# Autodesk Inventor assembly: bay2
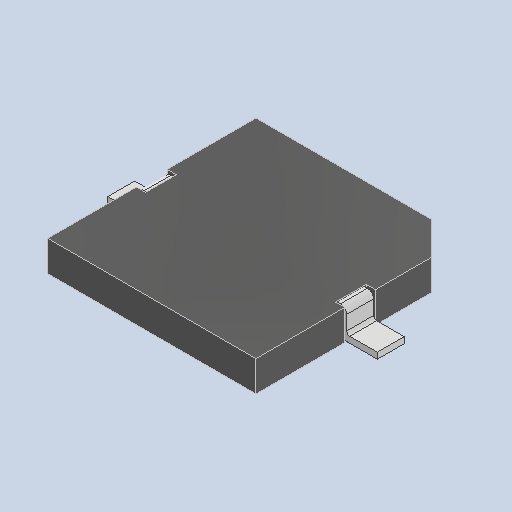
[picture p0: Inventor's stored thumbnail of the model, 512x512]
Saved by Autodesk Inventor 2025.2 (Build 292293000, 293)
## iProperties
Created: 2025-04
Part Number: bay2
Description: PART--DESC
Document SubType Name: Assembly
Designer: BennF
Author: BennF
Revision Number: NONE
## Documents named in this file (3)
- C:\Users\BennF\Nextcloud\Benutzer\CNC JarBeRi\existing parts\Electronics\RepRap A4988 Shied (USE WITHOUT ARDUINO)\reprap-a4988-1.snapshot.1\RepRap\RepRap\bay2_2.iam
- C:\Users\BennF\Nextcloud\Benutzer\CNC JarBeRi\existing parts\Electronics\RepRap A4988 Shied (USE WITHOUT ARDUINO)\reprap-a4988-1.snapshot.1\RepRap\RepRap\bay2 Geometry.ipt
- C:\Users\BennF\Nextcloud\Benutzer\CNC JarBeRi\existing parts\Electronics\RepRap A4988 Shied (USE WITHOUT ARDUINO)\reprap-a4988-1.snapshot.1\RepRap\RepRap\pin15.ipt
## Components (2 placed, 2 different names)
1. bay2 Geometry
2. pin15
